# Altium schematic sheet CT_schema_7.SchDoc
size 274 x 160 mm
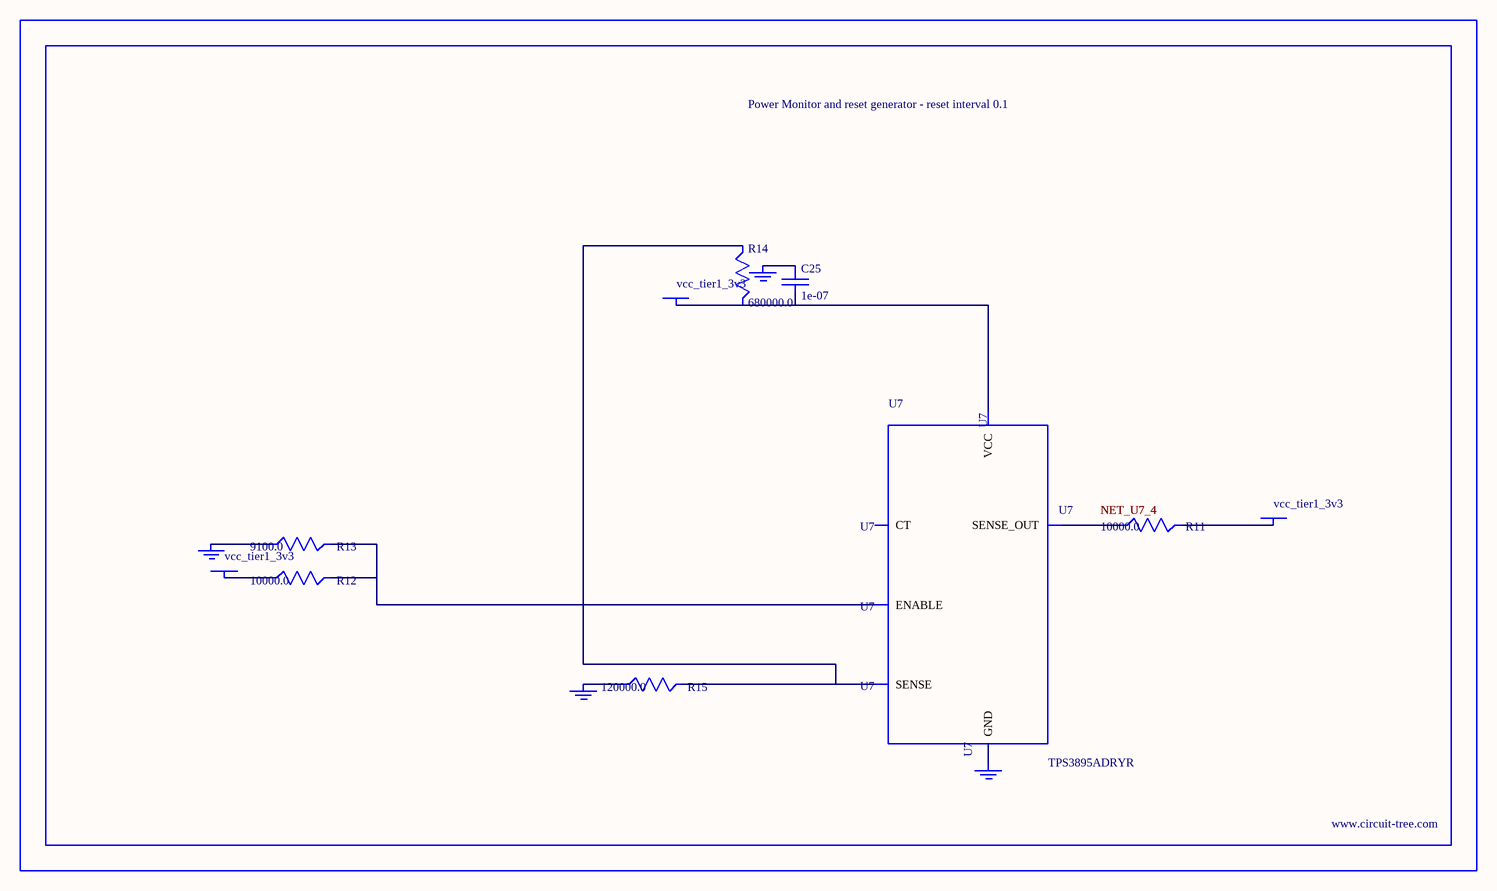
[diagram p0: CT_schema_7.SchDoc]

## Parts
BORDER6  (no value)
C25  1e-07  [C0402]
GND_INSTANCE_6_0  (no value)
GND_INSTANCE_6_1  (no value)
GND_INSTANCE_6_2  (no value)
GND_INSTANCE_6_3  (no value)
POWER_INSTANCE_6_0  vcc_tier1_3v3
POWER_INSTANCE_6_1  vcc_tier1_3v3
POWER_INSTANCE_6_2  vcc_tier1_3v3
R11  10000.0  [R0603]
R12  10000.0  [R0603]
R13  9100.0  [R0603]
R14  680000.0  [R0603]
R15  120000.0  [R0603]
U7  TPS3895ADRYR  [SON-6]

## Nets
NetC25_1: C25.1 GND_INSTANCE_6_2.0(GND)
NetC25_2: C25.2 POWER_INSTANCE_6_2.0(PWR) R14.2 U7.6(VCC)
NetGND_INSTANCE_6_0_0: GND_INSTANCE_6_0.0(GND) R13.1
NetGND_INSTANCE_6_1_0: GND_INSTANCE_6_1.0(GND) R15.1
NetGND_INSTANCE_6_3_0: GND_INSTANCE_6_3.0(GND) U7.2(GND)
NetPOWER_INSTANCE_6_0_0: POWER_INSTANCE_6_0.0(PWR) R12.1
NetPOWER_INSTANCE_6_1_0: POWER_INSTANCE_6_1.0(PWR) R11.2
NetR11_1: R11.1 U7.4(SENSE_OUT)
NetR12_2: R12.2 R13.2 U7.1(ENABLE)
NetR14_1: R14.1 R15.2 U7.3(SENSE)

Not connected (* = marked no-connect by the designer): U7 5(CT)

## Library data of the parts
BORDER6 = BORDER_PAGE6
C25 = C0402C104K3RACTU
GND_INSTANCE_6_0-GND_INSTANCE_6_3 = GND
POWER_INSTANCE_6_0-POWER_INSTANCE_6_2 = PWR
R11 R12 = RC0603JR-0710KL
R13 = RC0603JR-079K1L
R14 = RC0603JR-07680KL
R15 = RC0603JR-07120KL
